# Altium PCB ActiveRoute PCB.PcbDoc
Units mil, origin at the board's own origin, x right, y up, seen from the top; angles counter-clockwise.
Board outline 4257 x 3174 mil, 4 copper layers (Top Layer, Signal Layer 1, Signal Layer 2, Bottom Layer), stack 30.634 mil thick; 5 components, 18 nets, 44 pads, 0 vias.
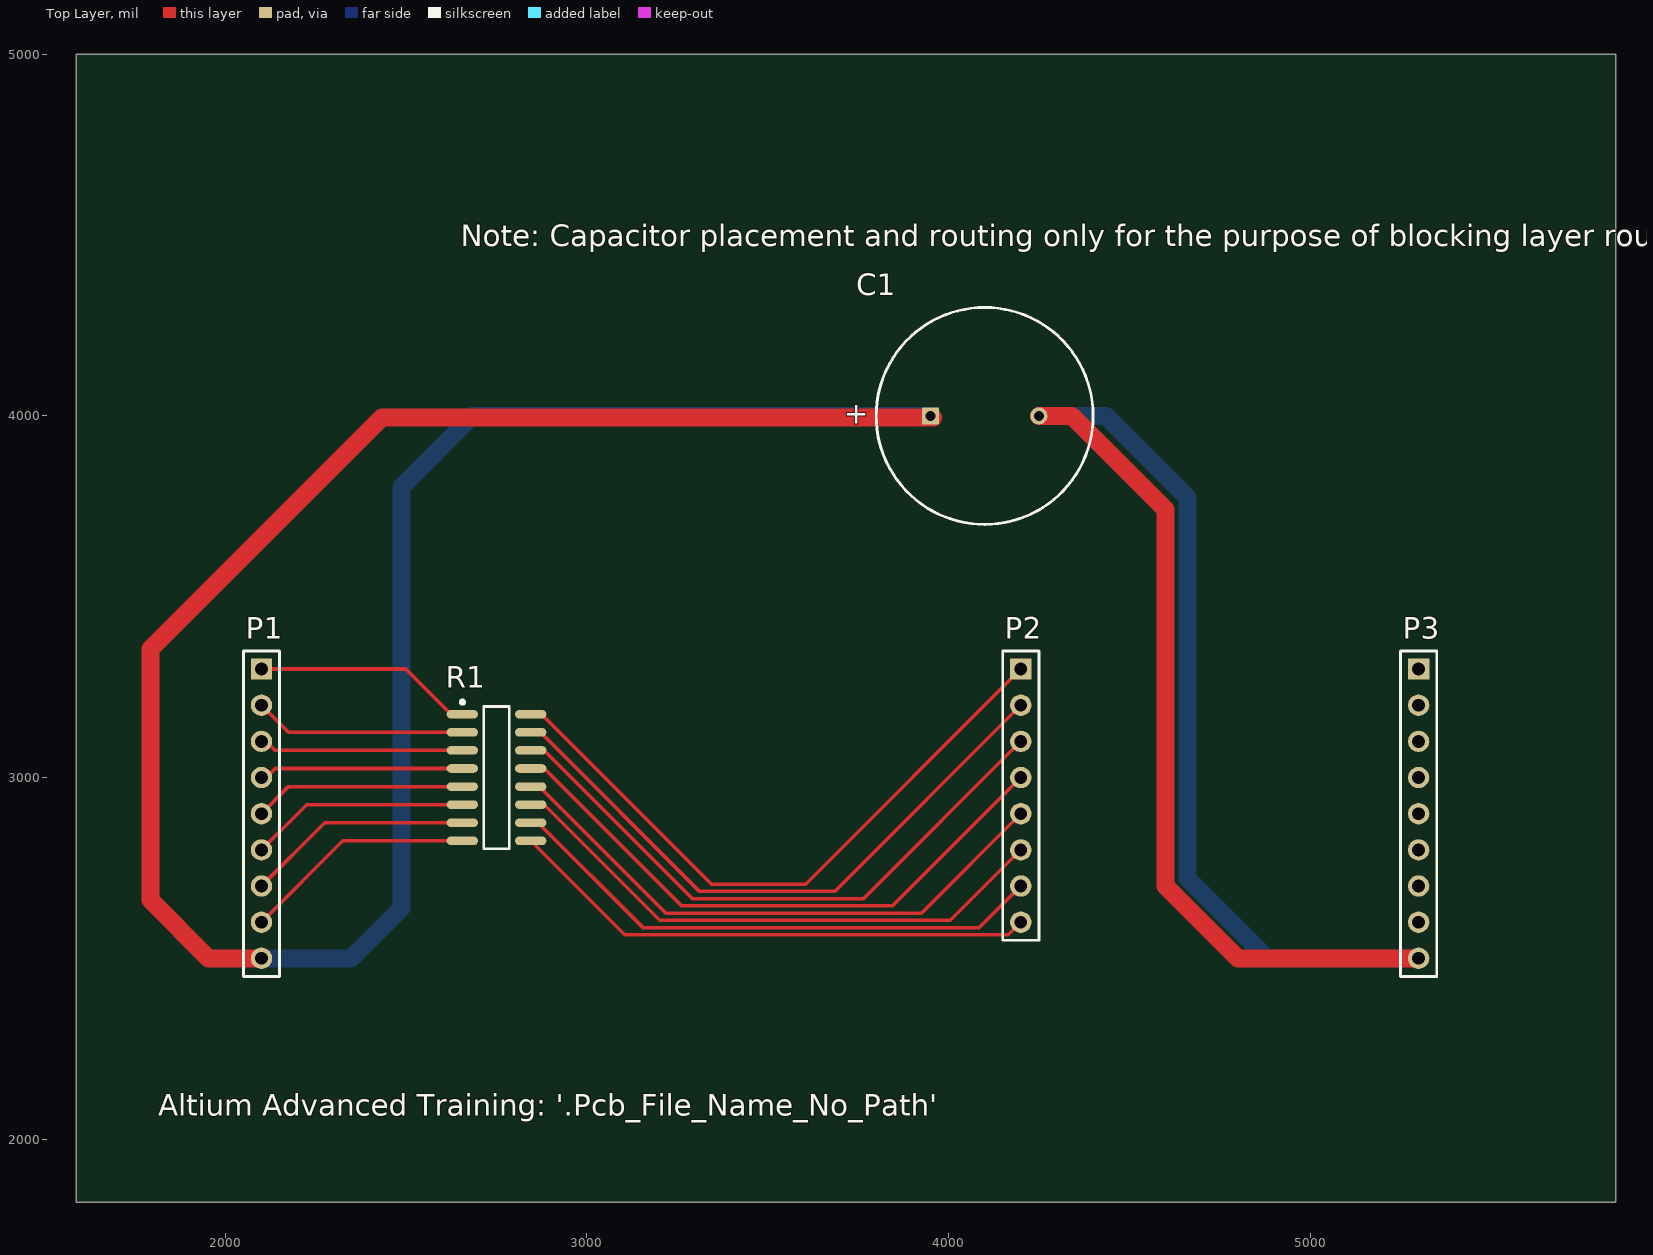
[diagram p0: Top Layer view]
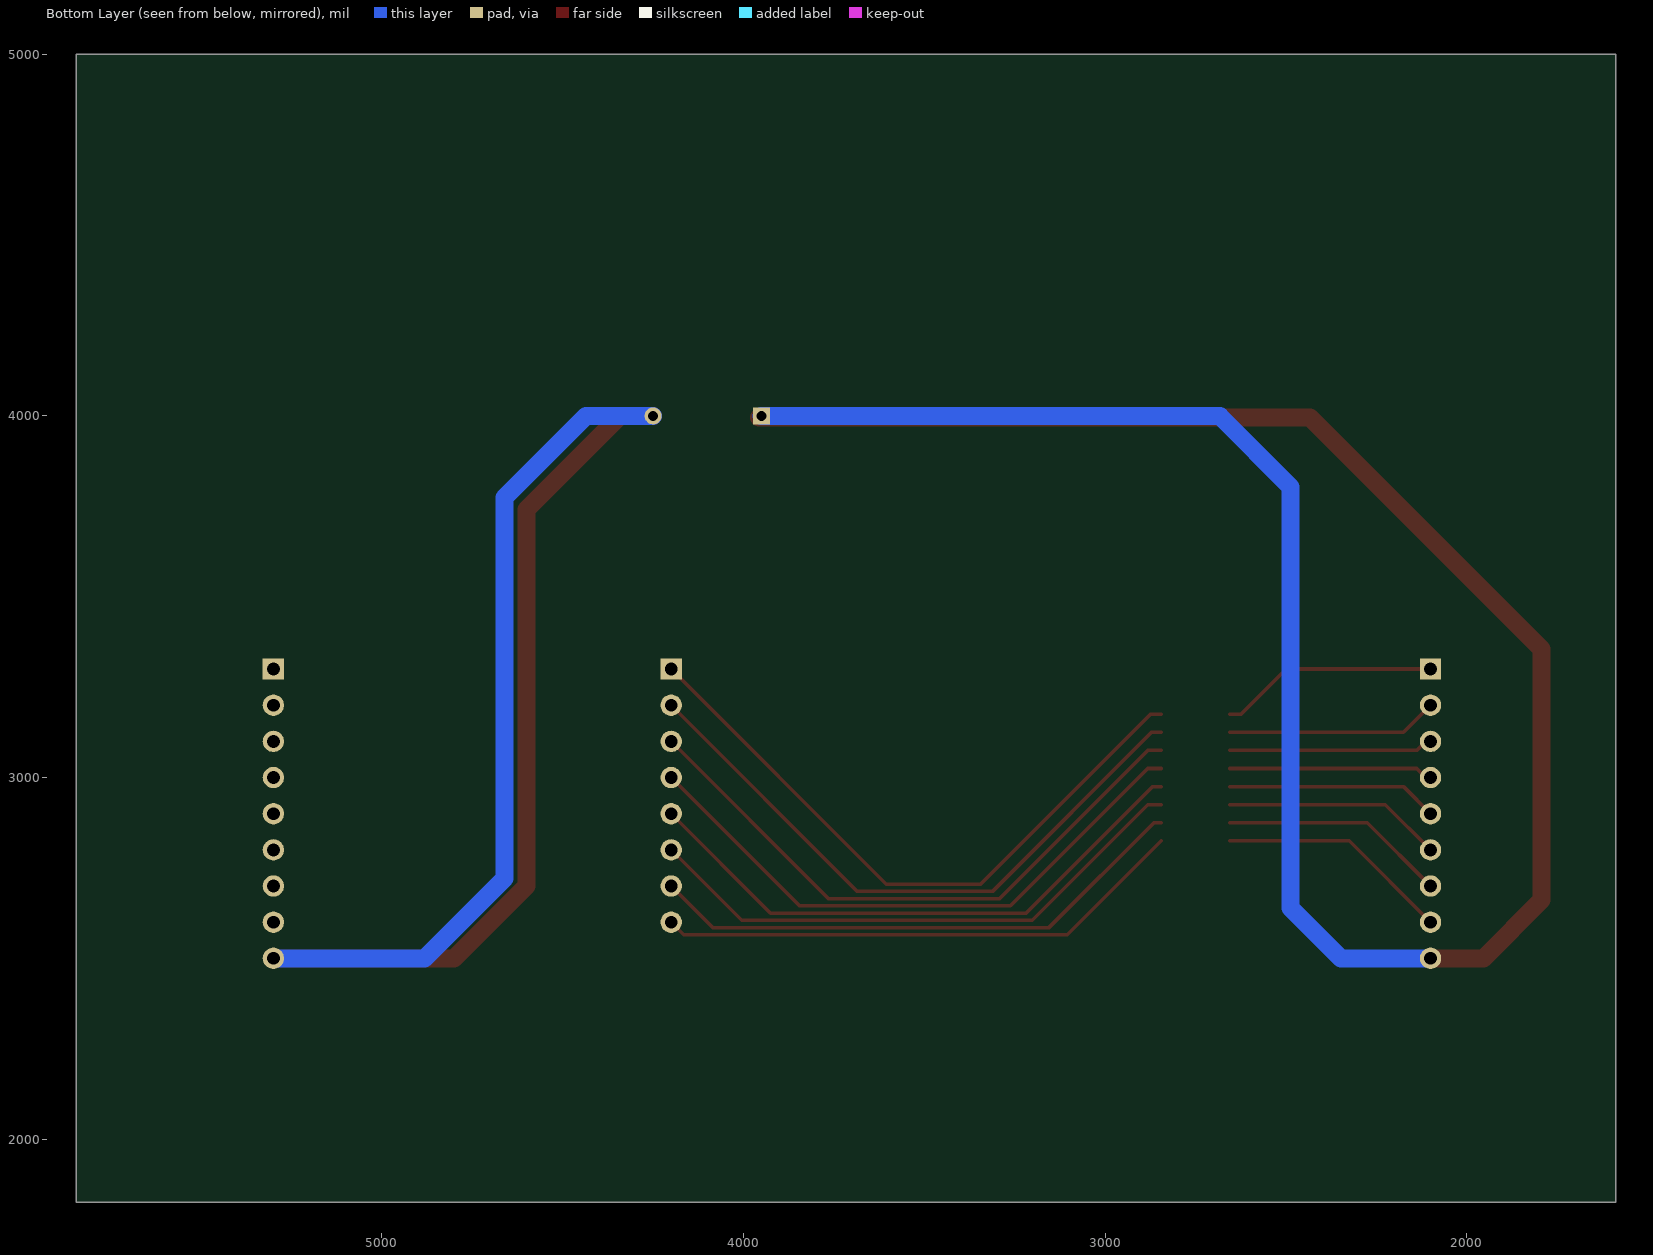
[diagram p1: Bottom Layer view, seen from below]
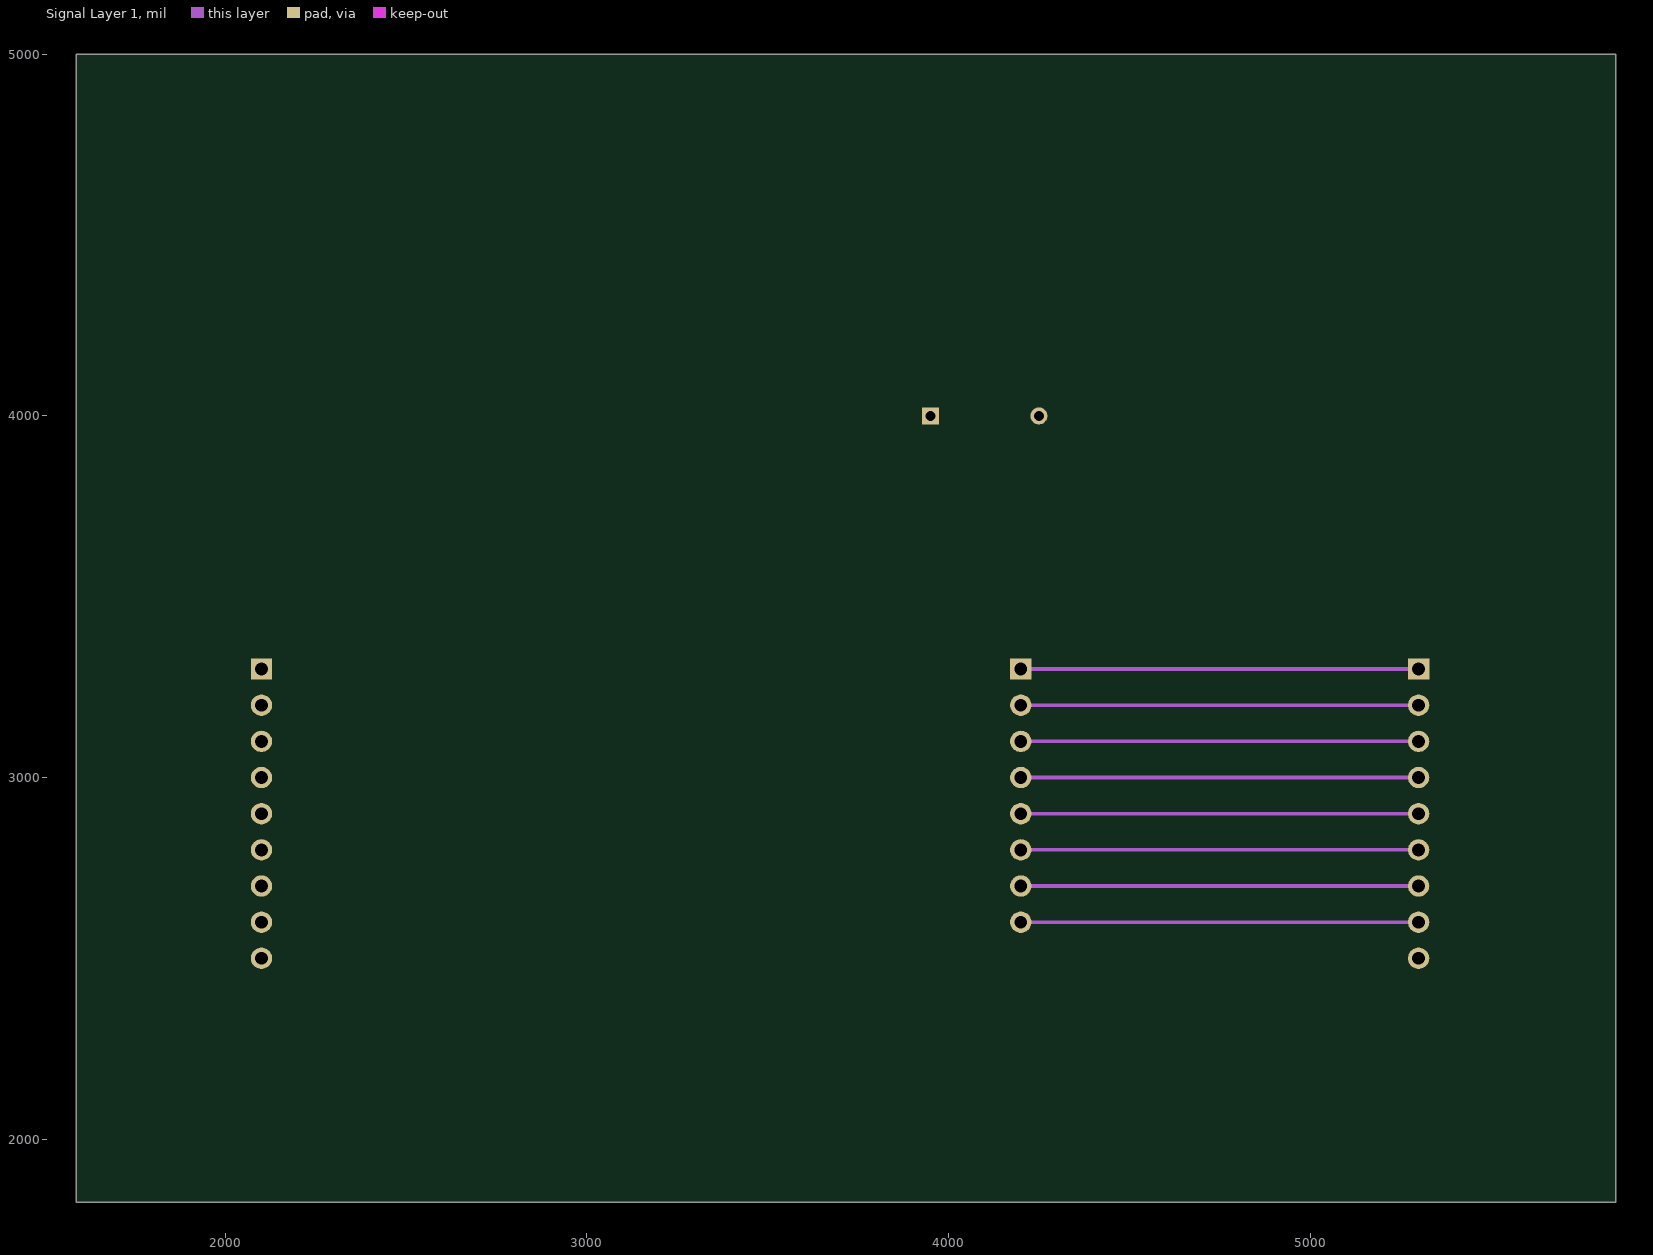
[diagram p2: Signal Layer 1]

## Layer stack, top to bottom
Top Solder: solder mask 0.4, Solder Resist, Dk 3.5
Top Layer: signal copper 1.4
Dielectric 1: core 10, FR-4, Dk 4.2
Signal Layer 1: signal copper 1.417
Dielectric 3: prepreg 5, Dk 4.2
Signal Layer 2: signal copper 1.417
Dielectric 2: core 10, Dk 4.2
Bottom Layer: signal copper 1.4
Bottom Solder: solder mask 0.4, Solder Resist, Dk 3.5

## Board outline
1588,1826 5845,1826 5845,5000 1588,5000

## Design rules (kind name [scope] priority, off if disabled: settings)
Clearance [All] p1: gap=10 ignorepadtopadclearanceinfootprint=FALSE except(0: Arc-Hole Track-Hole SMDPad-Hole THPad-Hole Via-Hole Fill-Hole Poly-Hole Region-Hole Text-Hole)
PolygonConnect [All] p1: connectstyle=Relief reliefconductorwidth=10 reliefentries=4 polygonreliefangle="90 Angle" airgapwidth=10
RoutingVias [All] p1: holewidth=28 width=50 viastyle="Through Hole" minholewidth=28 minwidth=50 maxholewidth=28 maxwidth=50
SolderMaskExpansion [All] p1: expansion=4 istentingtop=FALSE
Width [All] p1: maxlimit=60 minlimit=10 preferedwidth=10
30 further rules are at their usual default settings.

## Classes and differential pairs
net class P1nets: IOA0 IOA1 IOA2 IOA3 IOB0 IOB2 IOB5 IOB6
net class ADDR[7..0]: ADDR0 ADDR1 ADDR2 ADDR3 ADDR4 ADDR5 ADDR6 ADDR7

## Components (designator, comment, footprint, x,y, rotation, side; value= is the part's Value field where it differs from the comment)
C1 "Cap Pol1" RB7.6-15 4100,4000 r180 top value=100pF
P1 "Header 9" HDR1X9 2100,3300 r270 top
P2 "Header 8" HDR1X8 4200,3300 r270 top
P3 "Header 9" HDR1X9 5300,3300 r270 top
R1 "Res Pack1" SOIC16_N 2750,3000 r0 top value=1K

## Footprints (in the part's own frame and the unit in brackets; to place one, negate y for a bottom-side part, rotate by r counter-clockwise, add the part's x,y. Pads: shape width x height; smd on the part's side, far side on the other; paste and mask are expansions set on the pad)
HDR1X8 [mm] "Connector; Header; 8 Position"
  rect 1.5x1.5 hole 0.9: 1(0,0)
  round 1.5 hole 0.9: 2(2.54,0) 3(5.08,0) 4(7.62,0) 5(10.16,0) 6(12.7,0) 7(15.24,0) 8(17.78,0)
  silkscreen extent -1.27,-1.27 19.05,1.27
HDR1X9 [mm] "Connector; Header; 9 Position"
  rect 1.5x1.5 hole 0.9: 1(0,0)
  round 1.5 hole 0.9: 2(2.54,0) 3(5.08,0) 4(7.62,0) 5(10.16,0) 6(12.7,0) 7(15.24,0) 8(17.78,0) 9(20.32,0)
  silkscreen extent -1.27,-1.27 21.59,1.27
RB7.6-15 [mm] "Polarized Capacitor (Radial); 2 Leads"
  rect 1.2x1.2 hole 0.7: 1(3.81,0)
  round 1.2 hole 0.7: 2(-3.81,0)
  silkscreen extent -7.62,-7.62 7.62,7.62
SOIC16_N [mm] "SOIC, 16-Leads, Body 9.9x3.9mm, Pitch 1.27mm, IPC Medium Density"
  oval 2.2x0.6 smd: 1(-2.4,4.445) 2(-2.4,3.175) 3(-2.4,1.905) 4(-2.4,0.635) 5(-2.4,-0.635) 6(-2.4,-1.905) 7(-2.4,-3.175) 8(-2.4,-4.445) 9(2.4,-4.445) 10(2.4,-3.175) 11(2.4,-1.905) 12(2.4,-0.635) 13(2.4,0.635) 14(2.4,1.905) 15(2.4,3.175) 16(2.4,4.445)
  silkscreen extent -2.52,-5 0.9,5.42, body extent -2,-5 2,5, height 1.91

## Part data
C1: "Polarized Capacitor (Radial)"
P1 P3: "Header, 9-Pin"
P2: "Header, 8-Pin"
R1: "Isolated Resistor Network - Parts"

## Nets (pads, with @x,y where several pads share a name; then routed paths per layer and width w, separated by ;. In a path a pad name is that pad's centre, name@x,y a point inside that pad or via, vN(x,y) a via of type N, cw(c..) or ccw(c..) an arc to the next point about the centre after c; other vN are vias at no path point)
ADDR0: P2.1 P3.1 R1.16 | length 2896.6
  Top Layer w10: R1.16 2874.61,3175 3344.55,2705.06 3605.06,2705.06 P2.1
  Signal Layer 1 w10: P2.1 P3.1
ADDR1: P2.2 P3.2 R1.15 | length 2851
  Top Layer w10: R1.15 2871.52,3125 3311.46,2685.06 3685.06,2685.06 P2.2
  Signal Layer 1 w10: P2.2 P3.2
ADDR2: P2.3 P3.3 R1.14 | length 2805.5
  Top Layer w10: R1.14 2881.89,3075 3291.83,2665.06 3765.06,2665.06 P2.3
  Signal Layer 1 w10: P2.3 P3.3
ADDR3: P2.4 P3.4 R1.13 | length 2759.9
  Top Layer w10: R1.13 2881.89,3025 3261.83,2645.06 3845.06,2645.06 P2.4
  Signal Layer 1 w10: P2.4 P3.4
ADDR4: P2.5 P3.5 R1.12 | length 2714.3
  Top Layer w10: R1.12 2868.54,2975 3218.48,2625.06 3925.06,2625.06 P2.5
  Signal Layer 1 w10: P2.5 P3.5
ADDR5: P2.6 P3.6 R1.11 | length 2668.8
  Top Layer w10: R1.11 2881.89,2925 3201.83,2605.06 4005.06,2605.06 P2.6
  Signal Layer 1 w10: P2.6 P3.6
ADDR6: P2.7 P3.7 R1.10 | length 2623.2
  Top Layer w10: R1.10 2864.91,2875 3154.85,2585.06 4085.06,2585.06 P2.7
  Signal Layer 1 w10: P2.7 P3.7
ADDR7: P2.8 P3.8 R1.9 | length 2577.7
  Top Layer w10: R1.9 3104.43,2565.06 4165.06,2565.06 P2.8
  Signal Layer 1 w10: P2.8 P3.8
GND: C1.2 P3.9 | length 4569.3
  Top Layer w50: C1.2 4341,4000 4600,3741 4600,2700 4800,2500 P3.9
  Bottom Layer w50: C1.2 4435,4000 4661,3774 4661,2721 4882,2500 P3.9
IOA0: P1.1 R1.1 | length 607.3
  Top Layer w10: P1.1 2499.02,3300 2624.02,3175 R1.1
IOA1: P1.2 R1.2 | length 586.6
  Top Layer w10: P1.2 2175,3125 R1.2
IOA2: P1.3 R1.3 | length 565.9
  Top Layer w10: P1.3 2112.97,3100 2137.97,3075 R1.3
IOA3: P1.4 R1.4 | length 565.9
  Top Layer w10: P1.4 2112.97,3000 2137.97,3025 R1.4
IOB0: P1.5 R1.5 | length 586.6
  Top Layer w10: P1.5 2175,2975 R1.5
IOB2: P1.6 R1.6 | length 607.3
  Top Layer w10: P1.6 2225,2925 R1.6
IOB5: P1.7 R1.7 | length 628
  Top Layer w10: P1.7 2275,2875 R1.7
IOB6: P1.8 R1.8 | length 648.7
  Top Layer w10: P1.8 2325,2825 R1.8
VCC: C1.1 P1.9 | length 6651.5
  Top Layer w50: P1.9 1954,2500 1793,2661 1793,3356 2433,3996 C1.1@3957,3996
  Bottom Layer w50: P1.9 2348,2500 2487,2639 2487,3804 2683,4000 C1.1

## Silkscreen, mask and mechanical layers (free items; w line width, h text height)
Top Overlay:
  text "Note: Capacitor placement and routing only for the purpose of blocking layer routing." at 2651,4469 h60
  text "Altium Advanced Training: '.Pcb_File_Name_No_Path'" at 1815,2063.99 h60
Mechanical 1:
  lines w10: 3100,3000 3100,2600 3200,2500 3700,2500 3800,2600 3800,3000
